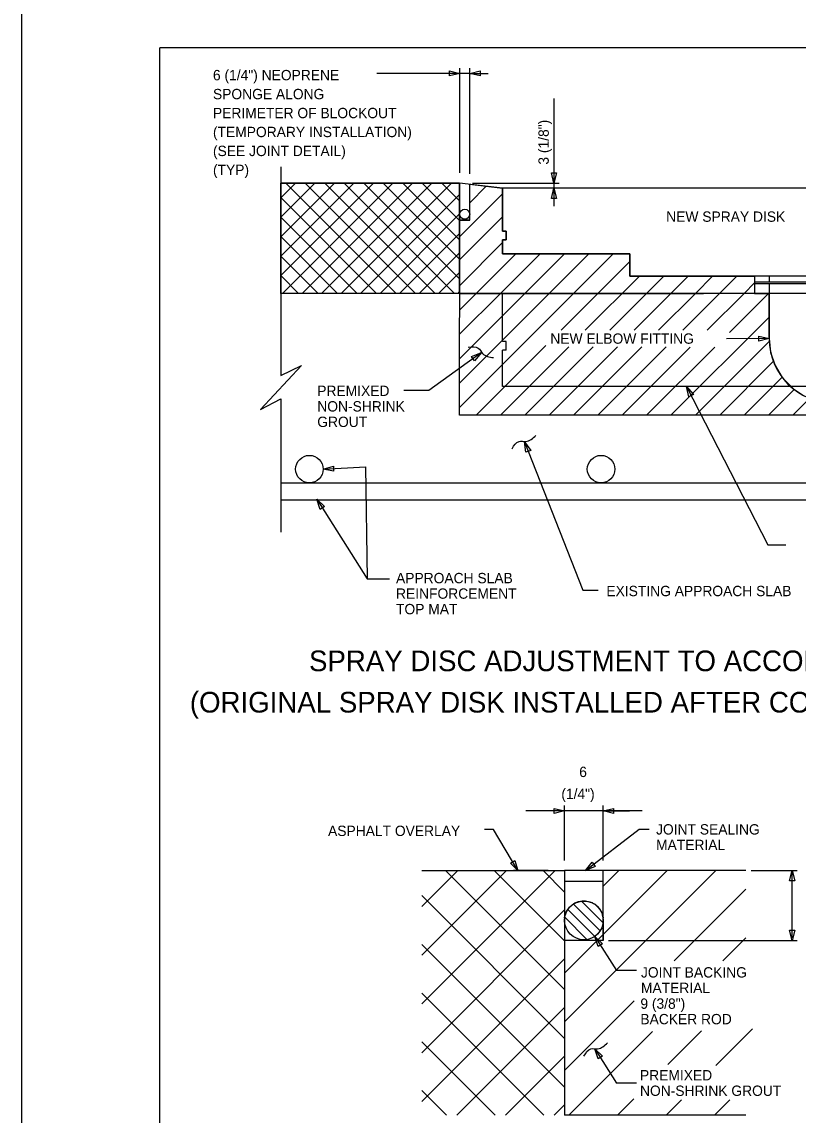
# Model space of a CAD drawing. Extents: x 3239 to 4230, y -4276 to -2494.
# Drawn here: x 3239 to 3464.4, y -4007.1 to -3689.8 of the extents above; entities that cross this region are included whole.
import ezdxf

# ---------------------------------------------------------------- set-up
doc = ezdxf.new("R2010")
doc.units = 0
for name, color, linetype in [('1', 7, 'Continuous'), ('2', 7, 'Continuous'), ('3', 7, 'Continuous'), ('PLT-BNDY', 7, 'Continuous')]:
    doc.layers.add(name, color=color, linetype=linetype)

msp = doc.modelspace()

# ---------------------------------------------------------------- linework, layer by layer
at = {"layer": '1'}
for p, q in [((3399.15, -3945.79), (3406.91, -3953.56)), ((3401.49, -3944.95), (3407.76, -3951.22)), ((3396.63, -3949.63), (3403.07, -3956.08)), ((3397.53, -3947.36), (3405.35, -3955.17)), ((3405.41, -3955.13), (3406.77, -3953.77))]:
    msp.add_line(p, q, dxfattribs=at)
msp.add_lwpolyline([(3396.55, -3936.1), (3396.55, -3949.81), (3396.87, -3948.48), (3397.29, -3947.68), (3398.02, -3946.66), (3398.79, -3945.98), (3399.58, -3945.48), (3400.63, -3945.07), (3401.68, -3944.88), (3402.67, -3944.88), (3403.91, -3945.13), (3405.4, -3945.85), (3406.05, -3946.4), (3406.63, -3947.05), (3407.04, -3947.63), (3407.49, -3948.58), (3407.79, -3949.83), (3407.8, -3936.1)], close=True, dxfattribs=at)
msp.add_circle((3402.18, -3950.53), 5.62, dxfattribs=at)
at = {"layer": '2'}
for p, q in [((3279.03, -4261.29), (3279.03, -3697.29)), ((4065.03, -3697.29), (3279.03, -3697.29)), ((3369.19, -3704.73), (3342.05, -3704.73)), ((3366.17, -3733.57), (3366.17, -3703.23)), ((3369.04, -3733.93), (3369.04, -3703.23)), ((3369.04, -3704.73), (3374.39, -3704.73)), ((3393.48, -3711.98), (3393.48, -3743.26)), ((3314.21, -3731.87), (3314.21, -3792.42)), ((3366.07, -3736.57), (3314.21, -3736.57)), ((3314.21, -3740.81), (3318.45, -3736.57)), ((3314.21, -3746.47), (3324.11, -3736.57)), ((3314.21, -3752.13), (3329.76, -3736.57)), ((3314.21, -3757.79), (3335.42, -3736.57)), ((3314.21, -3763.44), (3341.08, -3736.57)), ((3314.73, -3768.57), (3346.73, -3736.57)), ((3315.66, -3736.57), (3347.66, -3768.57)), ((3320.39, -3768.57), (3352.39, -3736.57)), ((3321.31, -3736.57), (3353.31, -3768.57)), ((3326.05, -3768.57), (3358.05, -3736.57)), ((3326.97, -3736.57), (3358.97, -3768.57)), ((3331.7, -3768.57), (3363.7, -3736.57)), ((3332.63, -3736.57), (3364.63, -3768.57)), ((3338.28, -3736.57), (3366.07, -3764.36)), ((3343.94, -3736.57), (3366.07, -3758.7)), ((3349.6, -3736.57), (3366.07, -3753.05)), ((3355.25, -3736.57), (3366.07, -3747.39)), ((3360.91, -3736.57), (3366.07, -3741.73)), ((3378.57, -3738.07), (3366.07, -3736.57)), ((3366.07, -3768.57), (3366.07, -3736.57)), ((3369.04, -3747.29), (3369.04, -3736.93)), ((3369.86, -3736.57), (3394.98, -3736.57)), ((3337.36, -3768.57), (3366.07, -3739.86)), ((3366.07, -3738.07), (3366.07, -3768.57)), ((3366.16, -3752.09), (3378.57, -3739.68)), ((3369.04, -3742.27), (3373.81, -3737.5)), ((3378.57, -3750.57), (3378.57, -3738.07)), ((3378.57, -3750.57), (3378.57, -3738.07)), ((3506.07, -3738.07), (3378.57, -3738.07)), ((3314.21, -3740.78), (3342, -3768.57)), ((3314.21, -3746.44), (3336.34, -3768.57)), ((3343.02, -3768.57), (3366.07, -3745.52)), ((3366.07, -3758.84), (3378.57, -3746.34)), ((3369.04, -3747.29), (3366.17, -3747.29)), ((3314.21, -3752.1), (3330.69, -3768.57)), ((3348.68, -3768.57), (3366.07, -3751.18)), ((3379.57, -3750.57), (3378.57, -3750.57)), ((3379.57, -3750.57), (3378.57, -3750.57)), ((3379.57, -3753.07), (3378.57, -3753.07)), ((3378.57, -3757.07), (3378.57, -3753.07)), ((3378.57, -3757.07), (3378.57, -3753.07)), ((3378.57, -3753.07), (3379.57, -3753.07)), ((3379.32, -3753.07), (3379.57, -3752.82)), ((3379.57, -3753.07), (3379.57, -3750.57)), ((3379.57, -3753.07), (3379.57, -3750.57)), ((3366.14, -3766.26), (3378.57, -3753.82)), ((3314.21, -3757.75), (3325.03, -3768.57)), ((3354.33, -3768.57), (3366.07, -3756.83)), ((3366.07, -3801.65), (3410.65, -3757.07)), ((3366.1, -3787.53), (3396.55, -3757.07)), ((3366.12, -3773.36), (3382.41, -3757.07)), ((3377.96, -3768.57), (3389.46, -3757.07)), ((3415.47, -3757.07), (3378.57, -3757.07)), ((3392.1, -3768.57), (3403.6, -3757.07)), ((3406.25, -3768.57), (3415.47, -3759.35)), ((3415.47, -3763.57), (3415.47, -3757.07)), ((3359.99, -3768.57), (3366.07, -3762.49)), ((3314.21, -3763.41), (3319.37, -3768.57)), ((3402.58, -3779.29), (3418.3, -3763.57)), ((3469.21, -3763.57), (3415.47, -3763.57)), ((3468.97, -3763.57), (3415.47, -3763.57)), ((3439.21, -3763.57), (3415.57, -3763.57)), ((3416.72, -3779.29), (3432.44, -3763.57)), ((3420.39, -3768.57), (3425.39, -3763.57)), ((3430.87, -3779.29), (3446.58, -3763.57)), ((3434.53, -3768.57), (3439.53, -3763.57)), ((3448.67, -3768.57), (3451.73, -3765.52)), ((3451.73, -3763.57), (3451.73, -3765.2)), ((3451.73, -3765.2), (3469.21, -3765.2)), ((3451.73, -3765.7), (3469.21, -3765.7)), ((3451.73, -3765.7), (3451.73, -3768.57)), ((3455.94, -3763.57), (3455.94, -3765.2)), ((3455.94, -3765.7), (3455.94, -3768.57)), ((3366.07, -3768.57), (3314.21, -3768.57)), ((3365.65, -3768.57), (3366.07, -3768.15)), ((3447.87, -3768.57), (3366.07, -3768.57)), ((3366.07, -3768.57), (3436.87, -3768.57)), ((3366.09, -3794.59), (3392.1, -3768.57)), ((3366.11, -3780.42), (3377.96, -3768.57)), ((3378.57, -3782.57), (3378.57, -3768.57)), ((3395.53, -3779.29), (3406.25, -3768.57)), ((3409.67, -3779.29), (3420.39, -3768.57)), ((3423.82, -3779.29), (3434.53, -3768.57)), ((3437.96, -3779.29), (3448.67, -3768.57)), ((3444.4, -3779.97), (3455.79, -3768.57)), ((3518.47, -3768.57), (3447.87, -3768.57)), ((3455.94, -3781.7), (3455.94, -3768.57)), ((3427.44, -3803.94), (3455.94, -3775.45)), ((3455.94, -3781.7), (3443.58, -3781.73)), ((3370.87, -3803.94), (3391.13, -3783.69)), ((3377.97, -3803.94), (3397.83, -3784.08)), ((3379.57, -3782.57), (3378.57, -3782.57)), ((3379.57, -3785.07), (3379.57, -3782.57)), ((3385.02, -3803.94), (3404.88, -3784.08)), ((3392.11, -3803.94), (3411.97, -3784.08)), ((3399.16, -3803.94), (3419.02, -3784.08)), ((3406.21, -3803.94), (3426.07, -3784.08)), ((3413.3, -3803.94), (3433.07, -3784.17)), ((3420.39, -3803.94), (3440.14, -3784.2)), ((3434.54, -3803.94), (3455.96, -3782.52)), ((3378.57, -3795.57), (3378.57, -3785.07)), ((3379.57, -3785.07), (3378.57, -3785.07)), ((3320.24, -3789.51), (3308.34, -3802.3)), ((3314.21, -3792.42), (3320.24, -3789.51)), ((3441.59, -3803.94), (3457.24, -3788.29)), ((3448.68, -3803.94), (3459.69, -3792.93)), ((3506.07, -3795.57), (3378.57, -3795.57)), ((3455.73, -3803.94), (3463.21, -3796.46)), ((3308.34, -3802.3), (3314.21, -3799.17)), ((3314.21, -3799.17), (3314.21, -3837.88)), ((3462.82, -3803.94), (3467.71, -3799.05)), ((3652.12, -3823.61), (3314.21, -3823.61)), ((3652.12, -3828.61), (3314.21, -3828.61)), ((3396.55, -3933.2), (3396.55, -3917.21)), ((3407.8, -3933.2), (3407.8, -3917.21)), ((3396.55, -3918.78), (3385.31, -3918.78)), ((3396.55, -3918.78), (3389.99, -3918.78)), ((3407.8, -3918.78), (3396.55, -3918.78)), ((3419.05, -3918.78), (3407.8, -3918.78)), ((3407.8, -3918.78), (3415.42, -3918.78)), ((3355.14, -3936.1), (3396.55, -3936.1)), ((3355.14, -3946.51), (3365.54, -3936.1)), ((3355.14, -3960.65), (3379.68, -3936.1)), ((3355.14, -3974.79), (3393.82, -3936.1)), ((3362.03, -3936.1), (3396.55, -3970.63)), ((3376.17, -3936.1), (3396.55, -3956.49)), ((3391.8, -3936.1), (3381.7, -3936.1)), ((3390.31, -3936.1), (3396.55, -3942.35)), ((3396.55, -3936.1), (3396.55, -4007.05)), ((3396.55, -3965.85), (3426.3, -3936.1)), ((3396.55, -3979.99), (3440.44, -3936.1)), ((3407.79, -3940.61), (3412.3, -3936.1)), ((3449.21, -3936.1), (3407.8, -3936.1)), ((3407.8, -3956.38), (3407.8, -3936.1)), ((3450.71, -3936.1), (3464.11, -3936.1)), ((3462.61, -3955.57), (3462.61, -3936.1)), ((3407.8, -3939.29), (3396.55, -3939.29)), ((3396.55, -3939.29), (3396.55, -3949.79)), ((3355.14, -3943.36), (3396.55, -3984.77)), ((3428.38, -3962.31), (3449.21, -3941.47)), ((3355.14, -3988.93), (3396.55, -3947.52)), ((3407.8, -3950.55), (3407.8, -3956.38)), ((3405.33, -3955.19), (3411.6, -3965.12)), ((3442.52, -3962.31), (3449.21, -3955.62)), ((3355.14, -3957.5), (3396.55, -3998.92)), ((3404.39, -3956.38), (3396.55, -3956.38)), ((3396.55, -3956.38), (3396.55, -3993.26)), ((3404.54, -3956.38), (3404.46, -3956.38)), ((3407.8, -3956.38), (3404.63, -3956.38)), ((3409.3, -3956.38), (3464.11, -3956.38)), ((3355.14, -4003.07), (3396.55, -3961.66)), ((3417.47, -3965.12), (3411.6, -3965.12)), ((3355.14, -3971.64), (3390.55, -4007.05)), ((3396.55, -3994.14), (3416.8, -3973.89)), ((3365.3, -4007.05), (3396.55, -3975.8)), ((3397.78, -4007.05), (3422.05, -3982.78)), ((3426.58, -3992.4), (3436.34, -3982.63)), ((3440.51, -3992.6), (3451.08, -3982.03)), ((3355.14, -3985.78), (3376.4, -4007.05)), ((3405.33, -3987.8), (3411.6, -3997.74)), ((3379.45, -4007.05), (3396.55, -3989.94)), ((3355.14, -3999.93), (3362.26, -4007.05)), ((3417.47, -3997.74), (3411.6, -3997.74)), ((3411.92, -4007.05), (3416.67, -4002.3)), ((3426.06, -4007.05), (3430.54, -4002.58)), ((3440.06, -4007.05), (3444.53, -4002.58)), ((3393.59, -4007.05), (3396.55, -4004.09)), ((3449.21, -4007.05), (3396.55, -4007.05))]:
    msp.add_line(p, q, dxfattribs=at)
for points in [[(3363.17, -3703.98), (3366.17, -3704.73), (3363.17, -3705.48)], [(3372.04, -3705.48), (3369.04, -3704.73), (3372.04, -3703.98)], [(3394.23, -3733.57), (3393.48, -3736.57), (3392.73, -3733.57)], [(3314.21, -3736.57), (3366.07, -3736.57), (3366.07, -3768.57), (3314.21, -3768.57)], [(3392.73, -3741.07), (3393.48, -3738.07), (3394.23, -3741.07)], [(3452.94, -3780.96), (3455.94, -3781.7), (3452.94, -3782.46)], [(3369.57, -3786.89), (3372.45, -3785.75), (3370.45, -3788.11)], [(3432.67, -3798.58), (3431.97, -3795.57), (3434, -3797.9)], [(3385.34, -3814.69), (3384.94, -3811.63), (3386.73, -3814.15)], [(3329.53, -3820.18), (3326.5, -3819.59), (3329.45, -3818.69)], [(3325.65, -3831.26), (3324.68, -3828.33), (3326.92, -3830.46)], [(3393.55, -3918.03), (3396.55, -3918.78), (3393.55, -3919.53)], [(3410.8, -3919.53), (3407.8, -3918.78), (3410.8, -3918.03)], [(3382.14, -3933.14), (3383.03, -3936.1), (3380.85, -3933.91)], [(3405.49, -3934.86), (3402.66, -3936.1), (3404.57, -3933.68)], [(3461.86, -3939.1), (3462.61, -3936.1), (3463.36, -3939.1)], [(3406.3, -3958.12), (3405.33, -3955.19), (3407.56, -3957.32)], [(3463.36, -3953.38), (3462.61, -3956.38), (3461.86, -3953.38)], [(3406.3, -3990.74), (3405.33, -3987.8), (3407.56, -3989.94)]]:
    msp.add_lwpolyline(points, close=True, dxfattribs=at)
for points in [[(3554.37, -3803.94), (3366.07, -3803.94), (3366.17, -3747.29), (3369.04, -3747.29), (3369.04, -3736.93), (3378.57, -3738.07), (3378.57, -3750.57), (3379.57, -3750.57), (3379.57, -3753.07), (3378.57, -3753.07), (3378.57, -3757.07), (3415.47, -3757.07), (3415.47, -3763.57), (3451.73, -3763.57), (3451.73, -3768.57), (3455.94, -3768.57), (3455.94, -3768.57), (3455.94, -3781.7), (3455.94, -3781.7), (3456.38, -3785.72), (3457.65, -3789.5), (3459.75, -3793), (3462.98, -3796.31), (3465.89, -3798.21)], [(3372.45, -3785.75), (3357.12, -3796.73), (3349.87, -3796.73)], [(3431.97, -3795.57), (3455.55, -3841.53), (3460.78, -3841.53)], [(3384.94, -3811.63), (3401.85, -3854.68), (3406.32, -3854.68)], [(3326.5, -3819.59), (3338.75, -3818.94), (3339.3, -3851.46)], [(3324.68, -3828.33), (3339.3, -3851.46), (3339.3, -3851.46), (3345.78, -3851.46)], [(3383.03, -3936.1), (3375.94, -3924.18), (3373.34, -3924.18)], [(3402.66, -3936.1), (3418.18, -3924.1), (3421.16, -3924.1)], [(3407.8, -3939.31), (3407.8, -3939.29), (3396.55, -3939.29)], [(3396.55, -3949.79), (3396.87, -3948.48), (3397.29, -3947.68), (3398.02, -3946.66), (3398.79, -3945.98), (3399.58, -3945.48), (3400.63, -3945.07), (3401.68, -3944.88), (3402.67, -3944.88), (3403.91, -3945.13), (3404.37, -3945.35)], [(3404.88, -3945.6), (3405.4, -3945.85), (3406.05, -3946.4), (3406.63, -3947.05), (3407.04, -3947.63), (3407.49, -3948.58), (3407.61, -3949.09)]]:
    msp.add_lwpolyline(points, dxfattribs=at)
for centre, radius in [((3367.6, -3745.6), 1.43), ((3322.5, -3819.59), 4), ((3407.17, -3819.59), 4)]:
    msp.add_circle(centre, radius, dxfattribs=at)
for centre, radius, start, end in [((3474.62, -3781.7), 18.68, 180, 270), ((3402.18, -3950.53), 5.62, 61.2213, 67.0505), ((3402.18, -3950.53), 5.62, 359.8058, 14.8835)]:
    msp.add_arc(centre, radius, start, end, dxfattribs=at)
for points in [[(3368.62, -3784.22), (3371.52, -3784.46), (3372.76, -3786.01), (3375.93, -3787.22)], [(3381.35, -3813.67), (3383.34, -3811.54), (3385.33, -3811.54), (3388.25, -3809.82)], [(3402.17, -3989.92), (3404.16, -3987.8), (3406.15, -3987.8), (3409.07, -3986.07)]]:
    msp.add_spline(points, degree=3, dxfattribs=at)
at = {"layer": 'PLT-BNDY'}
msp.add_lwpolyline([(3239.03, -3682.29), (4080.03, -3682.29), (4080.03, -4276.29), (3239.03, -4276.29)], close=True, dxfattribs=at)

# ---------------------------------------------------------------- texts
at = {"layer": '1'}
msp.add_text('(1/4")', height=3, dxfattribs=at).set_placement((3395.62, -3915.31))
at = {"layer": '2'}
for s, height, p in [('6 (1/4") NEOPRENE ', 3, (3294.5, -3706.74)), ('SPONGE ALONG ', 3, (3294.5, -3712.24)), ('PERIMETER OF BLOCKOUT', 3, (3294.5, -3717.74)), ('(TEMPORARY INSTALLATION)', 3, (3294.5, -3723.24)), ('(SEE JOINT DETAIL) ', 3, (3294.5, -3728.74)), ('(TYP)', 3, (3294.5, -3734.24)), ('NEW SPRAY DISK', 3, (3426.07, -3747.81)), ('NEW ELBOW FITTING', 3, (3392.43, -3783.2)), ('PREMIXED', 3, (3324.78, -3798.36)), ('NON-SHRINK', 3, (3324.78, -3802.86)), ('GROUT', 3, (3324.78, -3807.36)), ('APPROACH SLAB', 3, (3347.64, -3852.7)), ('REINFORCEMENT', 3, (3347.64, -3857.2)), ('EXISTING APPROACH SLAB', 3, (3408.7, -3856.45)), ('TOP MAT', 3, (3347.64, -3861.7)), ('SPRAY DISC ADJUSTMENT TO ACCOMMODATE BITUMINOUS OVERLAY', 6, (3322.38, -3878.22)), ('(ORIGINAL SPRAY DISK INSTALLED AFTER CONSTRUCTION OF APPROACH SLAB)', 6, (3287.79, -3890.22)), ('ASPHALT OVERLAY', 3, (3327.91, -3926.05)), ('JOINT SEALING', 3, (3423.12, -3925.62)), ('MATERIAL', 3, (3423.12, -3930.12))]:
    msp.add_text(s, height=height, dxfattribs=at).set_placement(p)
msp.add_text('3 (1/8")', height=3, rotation=90, dxfattribs=at).set_placement((3391.98, -3731.22))
at = {"layer": '3'}
for s, p in [('6', (3400.82, -3908.94)), ('JOINT BACKING', (3418.73, -3967.12)), ('MATERIAL', (3418.73, -3971.62)), ('9 (3/8")', (3418.57, -3976.19)), ('BACKER ROD', (3418.57, -3980.69)), ('PREMIXED', (3418.46, -3996.97)), ('NON-SHRINK GROUT', (3418.46, -4001.47))]:
    msp.add_text(s, height=3, dxfattribs=at).set_placement(p)

doc.saveas('drawing.dxf')
